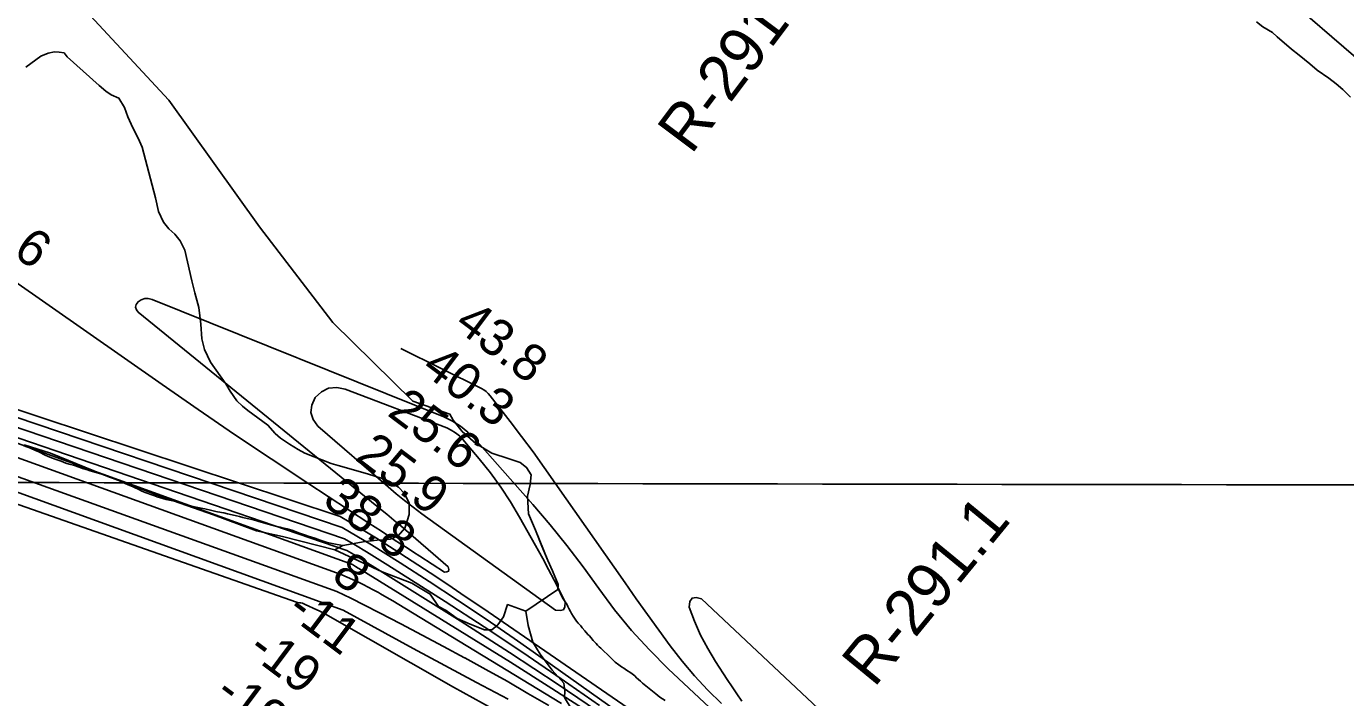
# Model space of a CAD drawing. Extents: x 3192986 to 3230865, y 867483 to 892886.
# Drawn here: x 3215272 to 3217672, y 878555 to 879776 of the extents above; entities that cross this region are included whole.
import ezdxf

# ---------------------------------------------------------------- set-up
doc = ezdxf.new("R2010")
doc.units = 0
for name, color, linetype in [('V-GRID-MAJR', 7, 'Continuous'), ('V-RIVR-EDGE', 7, 'Continuous'), ('V-RIVR-RANG', 7, 'Continuous'), ('V-RIVR-RANG-IDEN', 7, 'Continuous'), ('V-ROAD-CNTR', 7, 'Continuous'), ('V-SITE-VEGE', 7, 'Continuous'), ('V-TOPO-DPTH', 7, 'Continuous'), ('V-TOPO-MAJR', 7, 'Continuous'), ('V-TOPO-MINR', 7, 'Continuous'), ('V-TOPO-SHOR', 7, 'Continuous'), ('V-TOPO-WATR', 7, 'Continuous')]:
    doc.layers.add(name, color=color, linetype=linetype)

msp = doc.modelspace()

# ---------------------------------------------------------------- linework, layer by layer
at = {"layer": 'V-GRID-MAJR'}
msp.add_spline([(3197200.8, 878983.5), (3202427.8, 878971.7), (3207654.8, 878960.7), (3212881.9, 878950.4), (3218108.9, 878940.9), (3223335.9, 878932.2), (3228562.9, 878924.2)], degree=3, dxfattribs=at)
at = {"layer": 'V-RIVR-EDGE'}
for points in [[(3216181, 878711.8), (3216147.6, 878724), (3216140.6, 878701.5), (3216129.7, 878687.1), (3216119.2, 878678), (3216105.8, 878678.1), (3216079.7, 878688.1), (3216055.8, 878698.6), (3216035.9, 878713.5), (3216022, 878720.4), (3216007.2, 878743.1), (3215973.4, 878762.7), (3215919.5, 878783.3), (3215833.6, 878823.5), (3215738, 878847.6), (3215691.1, 878858.2), (3215612.5, 878887.5), (3215515.6, 878921.2), (3215411.4, 878960.6), (3215315.9, 878999.5), (3215268.1, 879014.4)], [(3216263.6, 878534.7), (3216251.5, 878555.1), (3216252, 878566.4), (3216250.3, 878580.8), (3216228.6, 878604.7), (3216206.9, 878633.9), (3216193.9, 878655.7), (3216184.9, 878686.1), (3216181, 878711.8)]]:
    msp.add_lwpolyline(points, dxfattribs=at)
at = {"layer": 'V-ROAD-CNTR'}
msp.add_lwpolyline([(3217944.3, 879501.1), (3217184.1, 880156.5)], dxfattribs=at)
at = {"layer": 'V-SITE-VEGE'}
for p, q in [((3215298.7, 879722), (3215312.1, 879727.3)), ((3215312.1, 879727.3), (3215323.6, 879729.7)), ((3215323.6, 879729.7), (3215331.8, 879729.3)), ((3215331.8, 879729.3), (3215340.9, 879727.9)), ((3215340.9, 879727.9), (3215346.7, 879720.7)), ((3215271.1, 879701.5), (3215298.7, 879722)), ((3215346.7, 879720.7), (3215404.8, 879668.6)), ((3215404.8, 879668.6), (3215417.1, 879658)), ((3215417.1, 879658), (3215426.5, 879651.5)), ((3215426.5, 879651.5), (3215440.6, 879645.5)), ((3215440.6, 879645.5), (3215450.8, 879628.4)), ((3215450.8, 879628.4), (3215457.1, 879611.3)), ((3215457.1, 879611.3), (3215465.9, 879591.2)), ((3215465.9, 879591.2), (3215475.6, 879572.5)), ((3215475.6, 879572.5), (3215483, 879556.1)), ((3215483, 879556.1), (3215486, 879544.4)), ((3215486, 879544.4), (3215507.5, 879464.2)), ((3215507.5, 879464.2), (3215512.6, 879439.1)), ((3215512.6, 879439.1), (3215521.6, 879420)), ((3215521.6, 879420), (3215531.5, 879407.5)), ((3215531.5, 879407.5), (3215542.1, 879397.7)), ((3215542.1, 879397.7), (3215551.8, 879385.6)), ((3215551.8, 879385.6), (3215560.6, 879368.5)), ((3215560.6, 879368.5), (3215573.3, 879313.3)), ((3215573.3, 879313.3), (3215578.9, 879291.2)), ((3215578.9, 879291.2), (3215586, 879264.6)), ((3215586, 879264.6), (3215589.8, 879233.9)), ((3215589.8, 879233.9), (3215591.6, 879207.6)), ((3215591.6, 879207.6), (3215596.6, 879188.1)), ((3215596.6, 879188.1), (3215607.3, 879165.3)), ((3215607.3, 879165.3), (3215635, 879125.8)), ((3215635, 879125.8), (3215642.9, 879112.3)), ((3215642.9, 879112.3), (3215655.3, 879094.6)), ((3215655.3, 879094.6), (3215665.2, 879085)), ((3215665.2, 879085), (3215675, 879076.9)), ((3215675, 879076.9), (3215711.8, 879050.6)), ((3215711.8, 879050.6), (3215724.9, 879035.3)), ((3215724.9, 879035.3), (3215734.7, 879026.9)), ((3215279.9, 879008.4), (3215268.1, 879013)), ((3215288.6, 879004.4), (3215279.9, 879008.4)), ((3215294.8, 879001.9), (3215288.6, 879004.4)), ((3215734.7, 879026.9), (3215751, 879015.8)), ((3215751, 879015.8), (3215766.7, 879006.4)), ((3215766.7, 879006.4), (3215778.8, 878999.2)), ((3215306.7, 878995.9), (3215294.8, 879001.9)), ((3215315.1, 878992.5), (3215306.7, 878995.9)), ((3215324.4, 878988.5), (3215315.1, 878992.5)), ((3215335.4, 878984.7), (3215324.4, 878988.5)), ((3215344.1, 878981.4), (3215335.4, 878984.7)), ((3215350.3, 878979.4), (3215344.1, 878981.4)), ((3215778.8, 878999.2), (3215826.8, 878980.9)), ((3215826.8, 878980.9), (3215839.5, 878977.3)), ((3215358.1, 878977.4), (3215350.3, 878979.4)), ((3215368.4, 878974), (3215358.1, 878977.4)), ((3215374.6, 878971.8), (3215368.4, 878974)), ((3215383.5, 878969), (3215374.6, 878971.8)), ((3215388.5, 878967.6), (3215383.5, 878969)), ((3215409.8, 878961.1), (3215388.5, 878967.6)), ((3215414.4, 878959.3), (3215409.8, 878961.1)), ((3215425.1, 878955.5), (3215414.4, 878959.3)), ((3215839.5, 878977.3), (3215893.1, 878961.8)), ((3215893.1, 878961.8), (3215919.5, 878953.1)), ((3215435.7, 878951.5), (3215425.1, 878955.5)), ((3215441.6, 878949.1), (3215435.7, 878951.5)), ((3215451, 878945.1), (3215441.6, 878949.1)), ((3215457.7, 878941.9), (3215451, 878945.1)), ((3215462.5, 878940), (3215457.7, 878941.9)), ((3215467.5, 878937.6), (3215462.5, 878940)), ((3215478, 878932.8), (3215467.5, 878937.6)), ((3215482.4, 878930.6), (3215478, 878932.8)), ((3215919.5, 878953.1), (3215932.9, 878948.1)), ((3215932.9, 878948.1), (3215949, 878937.7)), ((3215949, 878937.7), (3215959.3, 878926.8)), ((3215488.2, 878928.2), (3215482.4, 878930.6)), ((3215502.1, 878922.8), (3215488.2, 878928.2)), ((3215505.7, 878921.8), (3215502.1, 878922.8)), ((3215510.1, 878920.1), (3215505.7, 878921.8)), ((3215526.4, 878915.3), (3215510.1, 878920.1)), ((3215541.5, 878911.9), (3215526.4, 878915.3)), ((3215549.1, 878910.1), (3215541.5, 878911.9)), ((3215554.2, 878908.5), (3215549.1, 878910.1)), ((3215568.7, 878904.5), (3215554.2, 878908.5)), ((3215959.3, 878926.8), (3215968.7, 878909.1)), ((3215968.7, 878909.1), (3215968.7, 878888)), ((3215574.9, 878902.7), (3215568.7, 878904.5)), ((3215581.3, 878901.1), (3215574.9, 878902.7)), ((3215590.4, 878899.4), (3215581.3, 878901.1)), ((3215597.2, 878898.2), (3215590.4, 878899.4)), ((3215609.7, 878895.4), (3215597.2, 878898.2)), ((3215616.9, 878893.6), (3215609.7, 878895.4)), ((3215619.9, 878893), (3215616.9, 878893.6)), ((3215624.1, 878892.4), (3215619.9, 878893)), ((3215627.4, 878891.6), (3215624.1, 878892.4)), ((3215631.4, 878890.8), (3215627.4, 878891.6)), ((3215638, 878889.2), (3215631.4, 878890.8)), ((3215646.9, 878887.2), (3215638, 878889.2)), ((3215654.5, 878885.2), (3215646.9, 878887.2)), ((3215660.3, 878884), (3215654.5, 878885.2)), ((3215665.8, 878882.6), (3215660.3, 878884)), ((3215968.7, 878888), (3215960.7, 878863.1)), ((3215674, 878880.8), (3215665.8, 878882.6)), ((3215685.3, 878878), (3215674, 878880.8)), ((3215699.7, 878873.9), (3215685.3, 878878)), ((3215716.2, 878868.9), (3215699.7, 878873.9)), ((3215725.5, 878866.5), (3215716.2, 878868.9)), ((3215734.3, 878864.7), (3215725.5, 878866.5)), ((3215737.7, 878863.7), (3215734.3, 878864.7)), ((3215741, 878863.1), (3215737.7, 878863.7)), ((3215744, 878862.3), (3215741, 878863.1)), ((3215747, 878861.7), (3215744, 878862.3)), ((3215757, 878858.5), (3215747, 878861.7)), ((3215960.7, 878863.1), (3215948.4, 878848.8)), ((3215767.1, 878854.8), (3215757, 878858.5)), ((3215780.4, 878850.4), (3215767.1, 878854.8)), ((3215785.2, 878848.6), (3215780.4, 878850.4)), ((3215797.1, 878844.8), (3215785.2, 878848.6)), ((3215806.9, 878841.2), (3215797.1, 878844.8)), ((3215819.6, 878837.2), (3215806.9, 878841.2)), ((3215828.6, 878835.2), (3215819.6, 878837.2)), ((3215888.5, 878838.8), (3215848.1, 878831.7)), ((3215900.4, 878839.8), (3215888.5, 878838.8)), ((3215910.6, 878841), (3215900.4, 878839.8)), ((3215923.9, 878841.6), (3215910.6, 878841)), ((3215934.1, 878842.8), (3215923.9, 878841.6)), ((3215948.4, 878848.8), (3215934.1, 878842.8)), ((3215837.7, 878833.1), (3215828.6, 878835.2)), ((3215848.1, 878831.7), (3215837.7, 878833.1))]:
    msp.add_line(p, q, dxfattribs=at)
for points in [[(3215340.9, 879847), (3215531.2, 879641.9), (3215696.5, 879411.1), (3215829.7, 879237.4), (3215975.6, 879094.1), (3216042.8, 879070.3), (3216048.9, 879059.8), (3216065.3, 879038.8), (3216090.2, 879017.3), (3216118.8, 878999.2), (3216150.6, 878989.2), (3216170.5, 878982.5), (3216182.4, 878973.5), (3216190.6, 878960.2), (3216188.7, 878942.3), (3216184, 878921.1), (3216185.6, 878889.1), (3216198.7, 878859.3), (3216220.8, 878804.2), (3216229.7, 878785.3), (3216239.7, 878760.8), (3216239.4, 878751.4), (3216241.4, 878748.8), (3216243.2, 878745.3), (3216244.6, 878742.3), (3216246.4, 878738.7), (3216248.7, 878734.3), (3216251.1, 878730.9), (3216255.3, 878724.6), (3216257.3, 878720.8), (3216259.1, 878717), (3216261.9, 878711.6), (3216264.1, 878707.7), (3216266.8, 878703.1), (3216273.4, 878693.7), (3216276.2, 878690.5), (3216278.4, 878687.8), (3216280.8, 878685.2), (3216283.6, 878681.6), (3216288.5, 878676.2), (3216293.9, 878669.8), (3216296.5, 878667.1), (3216298.9, 878664.1), (3216303.4, 878658.9), (3216305.6, 878656.1), (3216308.6, 878653.1), (3216311.4, 878650.1), (3216314.6, 878647.2), (3216317.6, 878644.6), (3216320.6, 878641.4), (3216331.9, 878630.8), (3216336.5, 878626.1), (3216343.6, 878619.5), (3216350, 878614.3), (3216355.2, 878610.7), (3216359.1, 878608.6), (3216361.7, 878606.6), (3216364.3, 878604.8), (3216371.9, 878599.8), (3216379.2, 878594.2), (3216382.4, 878591), (3216389.8, 878584.7), (3216393.4, 878581.3), (3216405.5, 878571.1), (3216411.3, 878566.6), (3216417.2, 878561.4), (3216424.8, 878555.6), (3216434.7, 878549.7)], [(3217641.7, 879681.8), (3217620.5, 879696.3), (3217607.2, 879707.6), (3217587.7, 879723.7), (3217573.6, 879734.2), (3217547.8, 879756.7), (3217539.2, 879764.8), (3217522, 879775.3), (3217510.2, 879784.2)], [(3217681.5, 879647.2), (3217667.5, 879660.9), (3217655, 879671.3), (3217641.7, 879681.8)]]:
    msp.add_lwpolyline(points, dxfattribs=at)
at = {"layer": 'V-TOPO-DPTH'}
for points in [[(3215013.3, 879105), (3215865.4, 878796.8), (3215870.8, 878793.6), (3215876.2, 878790.4), (3215881.5, 878787.2), (3216153, 878619), (3216228.1, 878571.6), (3216302.6, 878523.2)], [(3215013.3, 879105), (3215865.4, 878796.8), (3215870.8, 878793.6), (3215876.2, 878790.4), (3215881.5, 878787.2), (3216153, 878619), (3216228.1, 878571.6), (3216302.6, 878523.2)], [(3216314.9, 878540.4), (3216245.5, 878588.9), (3216175.6, 878636.8), (3216105, 878683.5), (3216033.9, 878729.6), (3215929.9, 878795.9), (3215910.4, 878808.1), (3215890.8, 878820.2), (3215871, 878832.1), (3215851.1, 878843.8), (3215098.6, 879099.7)], [(3215074.7, 879022.2), (3215836.9, 878748), (3215862.4, 878735.7), (3215887.7, 878723), (3215915, 878709), (3215953.7, 878688.8), (3215992.4, 878668.5), (3216030.9, 878647.9), (3216069.4, 878627.2), (3216069.9, 878627), (3216108.4, 878605.8), (3216146.7, 878584.4), (3216184.8, 878562.4), (3216222.6, 878540.2)], [(3216222.6, 878540.2), (3216184.8, 878562.4), (3216146.7, 878584.4), (3216108.4, 878605.8), (3216069.9, 878627), (3216069.4, 878627.2), (3216030.9, 878647.9), (3215992.4, 878668.5), (3215953.7, 878688.8), (3215915, 878709), (3215887.7, 878723), (3215862.4, 878735.7), (3215836.9, 878748), (3215074.7, 879022.2)], [(3216119.5, 878534.7), (3216049.3, 878573.8), (3215816.6, 878706.5), (3215812.7, 878708.6), (3215808.7, 878710.8), (3215804.7, 878712.8), (3215800.6, 878714.7), (3215779.5, 878724.4), (3215777, 878725.4), (3215774.4, 878726.3), (3215771.7, 878727), (3215769, 878727.5), (3215766.3, 878727.9), (3215763.5, 878728.3), (3215008.1, 878993.6)], [(3216119.5, 878534.7), (3216049.3, 878573.8), (3215816.6, 878706.5), (3215812.7, 878708.6), (3215808.7, 878710.8), (3215804.7, 878712.8), (3215800.6, 878714.7), (3215779.5, 878724.4), (3215777, 878725.4), (3215774.4, 878726.3), (3215771.7, 878727), (3215769, 878727.5), (3215766.3, 878727.9), (3215763.5, 878728.3), (3215008.1, 878993.6)]]:
    msp.add_lwpolyline(points, dxfattribs=at)
at = {"layer": 'V-TOPO-MAJR'}
msp.add_lwpolyline([(3216619, 878439.5), (3216440, 878607.1), (3216405.7, 878641.4), (3216372.9, 878677), (3216342.4, 878714.5), (3216313.5, 878753.5), (3216285, 878792.9), (3216255.7, 878831.6), (3216225.1, 878869.2), (3216193.6, 878906.2), (3216088.1, 879025.6), (3216075.6, 879037.9), (3216062.2, 879048.8), (3216047.4, 879057.8), (3216031.6, 879065.5), (3215500.9, 879279.2), (3215494.1, 879280.6), (3215487.6, 879280.6), (3215481.4, 879278.5), (3215475.4, 879275), (3215472.3, 879270.2), (3215471, 879265.3), (3215472.4, 879260.5), (3215475.7, 879255.7), (3215919.4, 878895.3), (3215928, 878888.3), (3215936.5, 878881.3), (3215944.9, 878874.2), (3215953.3, 878867), (3216039.6, 878792.4), (3216040.9, 878787.9), (3216040.5, 878784.6), (3216037.5, 878783.3), (3216032.8, 878783.2), (3215988, 878812), (3215976.4, 878819.5), (3215964.8, 878827), (3215953.2, 878834.6), (3215941.6, 878842.1), (3215930, 878849.7), (3215918.5, 878857.3), (3215906.9, 878864.8), (3215895.3, 878872.4), (3215784.5, 878944.9), (3215717.7, 878989.1), (3215651.1, 879033.6), (3215585, 879078.8), (3215519.2, 879124.4), (3215245, 879316.2)], dxfattribs=at)
at = {"layer": 'V-TOPO-MINR'}
for points in [[(3216536.9, 878543.8), (3216511.9, 878568.6), (3216487.9, 878594.2), (3216465.3, 878621), (3216443.7, 878648.8), (3216422.9, 878677.2), (3216402.3, 878705.8), (3216381.8, 878734.5), (3216361.5, 878763.3), (3216234.5, 878945.1), (3216214.4, 878973.5), (3216194, 879001.7), (3216173.2, 879029.6), (3216152.2, 879057.3), (3216116.2, 879103.9), (3216112.7, 879107.8), (3216108.9, 879111.4), (3216104.6, 879114.5), (3216100.1, 879117.1), (3215953.8, 879189.8)], [(3216573.4, 878393.7), (3216102.7, 878717.2), (3216070.8, 878738.9), (3216038.8, 878760.6), (3216006.6, 878781.9), (3215974.3, 878803.2), (3215974.1, 878803.3), (3215941.7, 878824.1), (3215909.1, 878844.7), (3215876.2, 878864.7), (3215843.2, 878884.5), (3215110.3, 879126.6)], [(3216557, 878381.1), (3216210.8, 878626.6), (3216159.8, 878662.2), (3216108.6, 878697.3), (3216056.9, 878731.8), (3216004.9, 878765.8), (3215952.4, 878799.7), (3215926.3, 878816.3), (3215900.1, 878832.6), (3215873.6, 878848.6), (3215847.1, 878864.4), (3215093.7, 879118.8)], [(3216314.9, 878540.4), (3216245.5, 878588.9), (3216175.6, 878636.8), (3216105, 878683.5), (3216033.9, 878729.6), (3215929.9, 878795.9), (3215910.4, 878808.1), (3215890.8, 878820.2), (3215871, 878832.1), (3215851.1, 878843.8), (3215098.6, 879099.7)], [(3216053, 879036.7), (3216045.3, 879041.4), (3216037.1, 879045.3), (3215852.3, 879116.2), (3215836.8, 879118.7), (3215822.2, 879117.6), (3215809.3, 879110.9), (3215797.4, 879100.6), (3215791.5, 879086.9), (3215789.8, 879073.7), (3215794.2, 879061), (3215802.7, 879048.8), (3215930.2, 878938.1), (3215945.1, 878925.5), (3215960.3, 878913.1), (3215975.9, 878901.1), (3215991.6, 878889.4), (3216235.1, 878714.1), (3216243.3, 878713), (3216249.2, 878714.6), (3216251.8, 878720.2), (3216252.3, 878728.4), (3216242.6, 878748.4), (3216232.6, 878768.3), (3216222.3, 878788), (3216211.6, 878807.6), (3216169.7, 878882.9), (3216153.2, 878910.7), (3216135.6, 878937.8), (3216116.4, 878963.8), (3216096.3, 878989.1), (3216066.4, 879024.5), (3216060, 879031), (3216053, 879036.7)], [(3216328, 878518.7), (3216240, 878578.5), (3216151, 878636.9), (3216061.4, 878694.3), (3215906.4, 878791.7), (3215893.8, 878799.5), (3215881, 878807.3), (3215868.3, 878814.9), (3215855.4, 878822.4), (3215103.8, 879079.6)], [(3216245.7, 878544.3), (3215960.9, 878717.5), (3215949.9, 878724.1), (3215938.9, 878730.7), (3215927.8, 878737.1), (3215916.7, 878743.5), (3215912.7, 878745.7), (3215903.5, 878750.8), (3215894.2, 878755.8), (3215884.8, 878760.6), (3215875.4, 878765.3), (3215865.8, 878769.7), (3215856.2, 878774), (3215846.4, 878778), (3215836.6, 878781.9), (3215045.4, 879067.4)], [(3216149, 878551.9), (3216091.2, 878582.3), (3216033.6, 878613), (3215976.2, 878644.1), (3215848.9, 878713.6), (3215020.9, 879013.5)], [(3216222.6, 878540.2), (3216184.8, 878562.4), (3216146.7, 878584.4), (3216108.4, 878605.8), (3216069.9, 878627), (3216069.4, 878627.2), (3216030.9, 878647.9), (3215992.4, 878668.5), (3215953.7, 878688.8), (3215915, 878709), (3215887.7, 878723), (3215862.4, 878735.7), (3215836.9, 878748), (3215074.7, 879022.2)], [(3216119.5, 878534.7), (3216049.3, 878573.8), (3215816.6, 878706.5), (3215812.7, 878708.6), (3215808.7, 878710.8), (3215804.7, 878712.8), (3215800.6, 878714.7), (3215779.5, 878724.4), (3215777, 878725.4), (3215774.4, 878726.3), (3215771.7, 878727), (3215769, 878727.5), (3215766.3, 878727.9), (3215763.5, 878728.3), (3215008.1, 878993.6)], [(3216574.1, 878548.6), (3216565, 878561.4), (3216556.2, 878574.5), (3216547.5, 878587.6), (3216526.2, 878620.5), (3216512, 878644.2), (3216499, 878668.6), (3216487.9, 878693.8), (3216477.9, 878719.6), (3216479.6, 878729.4), (3216483.5, 878735.7), (3216490.8, 878736.7), (3216500.4, 878734.2), (3217016.6, 878249.5)]]:
    msp.add_lwpolyline(points, dxfattribs=at)
at = {"layer": 'V-TOPO-SHOR'}
for points in [[(3215340.9, 879847), (3215531.2, 879641.9), (3215696.5, 879411.1), (3215829.7, 879237.4), (3215975.6, 879094.1), (3216042.8, 879070.3)], [(3215833.6, 878823.5), (3215848.1, 878831.7), (3215888.5, 878838.8), (3215900.4, 878839.8), (3215910.6, 878841), (3215923.9, 878841.6), (3215934.1, 878842.8), (3215948.4, 878848.8), (3215960.7, 878863.1), (3215968.7, 878888), (3215968.7, 878909.1), (3215959.3, 878926.8), (3215949, 878937.7), (3215932.9, 878948.1), (3215919.5, 878953.1), (3215893.1, 878961.8), (3215839.5, 878977.3), (3215826.8, 878980.9), (3215778.8, 878999.2), (3215766.7, 879006.4), (3215751, 879015.8), (3215734.7, 879026.9), (3215724.9, 879035.3), (3215711.8, 879050.6), (3215675, 879076.9), (3215665.2, 879085), (3215655.3, 879094.6), (3215642.9, 879112.3), (3215635, 879125.8), (3215607.3, 879165.3), (3215596.6, 879188.1), (3215591.6, 879207.6), (3215589.8, 879233.9), (3215586, 879264.6), (3215578.9, 879291.2), (3215573.3, 879313.3), (3215567.1, 879339.8), (3215560.6, 879368.5), (3215551.8, 879385.6), (3215542.1, 879397.7), (3215531.5, 879407.5), (3215521.6, 879420), (3215512.6, 879439.1), (3215507.5, 879464.2), (3215486, 879544.4), (3215483, 879556.1), (3215475.6, 879572.5), (3215465.9, 879591.2), (3215457.1, 879611.3), (3215450.8, 879628.4), (3215440.6, 879645.5), (3215426.5, 879651.5), (3215417.1, 879658), (3215404.8, 879668.6), (3215346.7, 879720.7), (3215340.9, 879727.9), (3215331.8, 879729.3), (3215323.6, 879729.7), (3215312.1, 879727.3), (3215298.7, 879722), (3215271.1, 879701.5)], [(3216239.7, 878760.8), (3216229.7, 878785.3), (3216220.8, 878804.2), (3216210.3, 878830.4), (3216198.7, 878859.3), (3216185.6, 878889.1), (3216184, 878921.1), (3216188.7, 878942.3), (3216190.6, 878960.2), (3216182.4, 878973.5), (3216170.5, 878982.5), (3216150.6, 878989.2), (3216118.8, 878999.2), (3216090.2, 879017.3), (3216065.3, 879038.8), (3216048.9, 879059.8), (3216042.8, 879070.3)], [(3216239.7, 878760.8), (3216239.4, 878751.4), (3216181, 878711.8)]]:
    msp.add_lwpolyline(points, dxfattribs=at)
at = {"layer": 'V-TOPO-WATR'}
msp.add_lwpolyline([(3216302.6, 878523.2), (3216228.1, 878571.6), (3216153, 878619), (3215881.5, 878787.2), (3215876.2, 878790.4), (3215870.8, 878793.6), (3215865.4, 878796.8), (3215013.3, 879105)], dxfattribs=at)

# ---------------------------------------------------------------- texts
at = {"layer": 'V-RIVR-RANG'}
for s, rotation, p in [('38.6', 324.1583, (3215144.5, 879433.8)), ('43.8', 323.0083, (3216048.3, 879228.5)), ('40.3', 323.0083, (3215988.3, 879148.5)), ('25.6', 323.0083, (3215926.8, 879069.6)), ('25.9', 323.0083, (3215868.1, 878988.6)), ('38.8', 323.0083, (3215808.4, 878908.4)), ('8', 323.1471, (3215824.5, 878771)), ('-11', 323.1471, (3215742.8, 878707.3)), ('-19', 323.1471, (3215671.8, 878635.5)), ('-19', 323.1471, (3215611.8, 878555.5))]:
    msp.add_text(s, height=67, rotation=rotation, dxfattribs=at).set_placement(p)
at = {"layer": 'V-RIVR-RANG-IDEN'}
for s, rotation, p in [('R-291.3', 53.1472, (3216481.9, 879541.1)), ('R-291.1', 50.6501, (3216814.5, 878571.3))]:
    msp.add_text(s, height=83, rotation=rotation, dxfattribs=at).set_placement(p)

doc.saveas('drawing.dxf')
